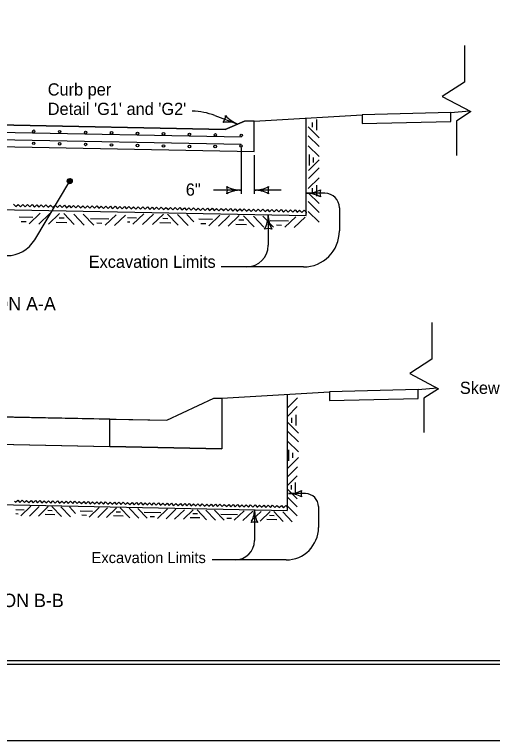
# Model space of a CAD drawing. Extents: x 10028 to 81668, y 6395 to 11634.
# Drawn here: x 14605 to 15231, y 7825 to 8776 of the extents above; entities that cross this region are included whole.
import ezdxf

# ---------------------------------------------------------------- set-up
doc = ezdxf.new("R2010")
doc.units = 0
for name, color, linetype in [('Default', 7, 'Continuous'), ('dsnCellElements', 7, 'Continuous'), ('dsnstdblockInterim', 7, 'Continuous'), ('dsnStdDimension', 7, 'Continuous'), ('ShtPlotIdentification', 7, 'Continuous')]:
    doc.layers.add(name, color=color, linetype=linetype)

msp = doc.modelspace()

# ---------------------------------------------------------------- linework, layer by layer
at = {"layer": 'Default'}
msp.add_lwpolyline([(13732.53, 9944.02), (16867.53, 9944.02), (16867.53, 7924.02), (13732.53, 7924.02)], close=True, dxfattribs=at)
at = {"layer": 'dsnCellElements'}
msp.add_line((14901.95, 8605.39), (14170.4, 8618.94), dxfattribs=at)
at = {"layer": 'dsnstdblockInterim'}
msp.add_lwpolyline([(13732.53, 9939.02), (16867.53, 9939.02), (16867.53, 7929.02), (13732.53, 7929.02)], close=True, dxfattribs=at)
at = {"layer": 'dsnStdDimension'}
msp.add_lwpolyline([(13628.03, 7824.52), (16972.03, 7824.52), (16972.03, 10408.52), (13628.03, 10408.52)], close=True, dxfattribs=at)
at = {"layer": 'ShtPlotIdentification'}
for p, q in [((15194.49, 8734.93), (15194.49, 8687.1)), ((15194.49, 8687.1), (15165.49, 8668.29)), ((15165.49, 8668.29), (15203.08, 8648.41)), ((15176.62, 8647.27), (15201.26, 8649.37)), ((15203.08, 8648.41), (15184.06, 8635.97)), ((14880.69, 8625.23), (14170.44, 8639.49)), ((14170.44, 8639.49), (14880.69, 8625.23)), ((14867.19, 8643.4), (14897.51, 8632.2)), ((14987.03, 8512.31), (14987.03, 8639.89)), ((14170.4, 8630), (14902.07, 8615.32)), ((14906.21, 8635.81), (14880.69, 8625.23)), ((14880.69, 8625.23), (14906.21, 8635.81)), ((14918.97, 8635.81), (14906.21, 8635.81)), ((14918.97, 8635.81), (14906.21, 8635.81)), ((14918.97, 8596.1), (14918.97, 8635.81)), ((14918.97, 8596.1), (14918.97, 8635.81)), ((14989.84, 8628.45), (15003.98, 8614.31)), ((15184.06, 8635.97), (15184.06, 8591.14)), ((14169.87, 8611.13), (14918.97, 8596.1)), ((14171.01, 8611.11), (14918.97, 8596.1)), ((14989.84, 8616.87), (15003.98, 8602.73)), ((14901.96, 8601.62), (14901.96, 8540.88)), ((14989.84, 8603.81), (15003.98, 8589.67)), ((14918.97, 8591.37), (14918.97, 8540.88)), ((14990.06, 8571.37), (15004.21, 8585.51)), ((14990.06, 8560.63), (15004.21, 8574.77)), ((14989.84, 8547.62), (15003.98, 8561.76)), ((14631.09, 8480.48), (14677.11, 8557.45)), ((14901.96, 8545.6), (14865.42, 8545.6)), ((14954.19, 8545.6), (14918.97, 8545.6)), ((14989.84, 8542.21), (15003.98, 8528.07)), ((15011.75, 8541.48), (14987.03, 8541.48)), ((14170.44, 8528.7), (14987.03, 8512.31)), ((14989.84, 8530.63), (15003.98, 8516.49)), ((15030.66, 8522.57), (15030.66, 8492.21)), ((14638.36, 8515.4), (14623.94, 8501.55)), ((14650.8, 8514.93), (14636.38, 8501.07)), ((14663.81, 8514.89), (14649.39, 8501.03)), ((14669.22, 8514.78), (14683.08, 8500.36)), ((14682.23, 8514.29), (14696.08, 8499.87)), ((14694.68, 8514.27), (14708.53, 8499.85)), ((14737.89, 8513.4), (14723.47, 8499.55)), ((14774.43, 8514.76), (14760.01, 8500.91)), ((14786.87, 8514.29), (14772.45, 8500.43)), ((14799.88, 8514.25), (14785.46, 8500.4)), ((14805.29, 8514.14), (14819.15, 8499.72)), ((14818.3, 8513.66), (14832.15, 8499.23)), ((14830.75, 8513.63), (14839.85, 8504.16)), ((14937.35, 8513.31), (14937.35, 8473.3)), ((14989.84, 8517.57), (15003.98, 8503.43)), ((14750.34, 8512.93), (14735.91, 8499.07)), ((14873.96, 8512.76), (14859.54, 8498.91)), ((14886.41, 8512.29), (14871.98, 8498.43)), ((14899.42, 8512.25), (14884.99, 8498.4)), ((14904.83, 8512.14), (14918.68, 8497.72)), ((14917.83, 8511.66), (14931.68, 8497.23)), ((14930.28, 8511.63), (14944.14, 8497.21)), ((14973.5, 8510.77), (14959.07, 8496.91)), ((14985.94, 8510.29), (14971.52, 8496.44)), ((14983.39, 8444.95), (14875.63, 8444.95)), ((15151.88, 8371.97), (15151.88, 8324.14)), ((15151.88, 8324.14), (15122.88, 8305.33)), ((15122.88, 8305.33), (15160.47, 8285.45)), ((15134.01, 8284.31), (15158.65, 8286.41)), ((15160.47, 8285.45), (15141.45, 8273.01)), ((14962.76, 8126.08), (14962.76, 8278.03)), ((14962.97, 8260.91), (14975.69, 8273.64)), ((15141.45, 8273.01), (15141.45, 8228.18)), ((14962.76, 8249.21), (14975.49, 8261.93)), ((14729.51, 8245.72), (14393.87, 8252.46)), ((14393.87, 8252.46), (14804.18, 8244.22)), ((14729.51, 8209.71), (14729.51, 8245.72)), ((14962.77, 8241.43), (14976.91, 8227.29)), ((14962.77, 8229.86), (14976.91, 8215.72)), ((14393.87, 8216.45), (14729.51, 8209.71)), ((14393.87, 8216.45), (14876.36, 8206.77)), ((14962.77, 8216.8), (14976.91, 8202.66)), ((14962.75, 8180.96), (14976.9, 8195.1)), ((14962.97, 8170.26), (14975.69, 8182.99)), ((14962.76, 8158.55), (14975.49, 8171.28)), ((14962.76, 8153.68), (14975.49, 8140.96)), ((14962.76, 8143.27), (14975.49, 8130.54)), ((14986.28, 8147.92), (14964.03, 8147.92)), ((14393.87, 8137.48), (14962.76, 8126.06)), ((14625.96, 8131.49), (14612.98, 8119.02)), ((14637.15, 8131.07), (14624.17, 8118.6)), ((14648.86, 8131.03), (14635.88, 8118.56)), ((14653.73, 8130.94), (14666.2, 8117.96)), ((14665.43, 8130.5), (14677.9, 8117.52)), ((14676.64, 8130.48), (14684.83, 8121.95)), ((14715.53, 8129.7), (14702.55, 8117.23)), ((14726.73, 8129.27), (14713.75, 8116.8)), ((14738.44, 8129.24), (14725.46, 8116.77)), ((14743.31, 8129.14), (14755.78, 8116.16)), ((14755.01, 8128.7), (14767.48, 8115.72)), ((14766.22, 8128.68), (14778.69, 8115.7)), ((14805.11, 8127.9), (14792.13, 8115.43)), ((14816.31, 8127.47), (14803.33, 8115)), ((14827.39, 8126.91), (14814.41, 8114.44)), ((14839.1, 8126.88), (14826.12, 8114.41)), ((14843.97, 8126.78), (14856.44, 8113.8)), ((14855.67, 8126.34), (14868.14, 8113.36)), ((14866.88, 8126.32), (14879.35, 8113.34)), ((14905.77, 8125.54), (14892.79, 8113.07)), ((14916.97, 8125.11), (14903.99, 8112.64)), ((14928.08, 8124.56), (14915.1, 8112.09)), ((14919.31, 8126.94), (14919.31, 8086.57)), ((14939.79, 8124.53), (14926.81, 8112.06)), ((14944.66, 8124.43), (14957.13, 8111.45)), ((14956.36, 8123.99), (14968.83, 8111.01)), ((14962.76, 8131.51), (14975.49, 8118.78)), ((15003.29, 8130.9), (15003.29, 8103.58)), ((14960.75, 8061.04), (14863.76, 8061.04))]:
    msp.add_line(p, q, dxfattribs=at)
for points in [[(14918.97, 8635.81), (15060.41, 8644.3), (15060.41, 8633.08), (15176.62, 8635.6), (15176.62, 8647.27), (15060.41, 8644.3)], [(15001.19, 8624.06), (15001.19, 8638.25)], [(14995.34, 8627.89), (14995.34, 8634.42)], [(14991.64, 8578.06), (14991.64, 8592.25)], [(14996.73, 8581.89), (14996.73, 8588.42)], [(14676.85, 8554.41), (14677.97, 8554.91), (14679.7, 8555.45), (14680.04, 8557.21), (14679.8, 8558.76), (14678.69, 8560.19), (14677.04, 8560.05), (14675.29, 8559.8), (14674.46, 8558.41), (14674.31, 8556.95), (14675.33, 8555.03), (14676.61, 8554.87), (14678.34, 8555.31), (14679.77, 8556.43), (14679.72, 8558.08), (14678.61, 8559.41), (14677.05, 8559.56), (14675.31, 8559.22), (14675.05, 8558.23), (14674.7, 8557.06), (14675.51, 8555.62), (14676.78, 8555.66), (14678.23, 8555.9), (14679.27, 8556.7), (14678.75, 8558.15), (14677.65, 8558.99), (14676.19, 8559.05), (14675.82, 8558.26), (14675.36, 8557.37), (14676.08, 8556.22), (14677.16, 8555.96), (14678.12, 8556.47), (14678.18, 8557.55), (14677.67, 8558.31), (14676.69, 8558.58), (14676.22, 8558.17), (14675.94, 8557.58), (14676.45, 8556.72), (14677.14, 8556.54), (14677.81, 8556.95), (14677.7, 8557.53), (14677.2, 8557.91), (14676.52, 8557.89), (14676.53, 8557.4), (14677.12, 8557.13)], [(15001.19, 8537.82), (15001.19, 8552.01)], [(14995.34, 8541.65), (14995.34, 8548.18)], [(14603.52, 8527.05), (14606.49, 8523.96), (14609.57, 8526.93), (14612.53, 8523.84), (14615.62, 8526.8), (14618.58, 8523.72), (14621.67, 8526.68), (14624.63, 8523.6), (14627.72, 8526.56), (14630.68, 8523.48), (14633.77, 8526.44), (14636.73, 8523.36), (14639.81, 8526.32), (14642.78, 8523.23), (14645.86, 8526.2), (14648.83, 8523.11), (14651.91, 8526.08), (14654.88, 8522.99), (14657.96, 8525.96), (14659.44, 8524.41)], [(14659.44, 8524.41), (14660.92, 8522.87), (14664.01, 8525.83), (14666.98, 8522.75), (14670.06, 8525.71), (14673.02, 8522.62), (14676.11, 8525.59), (14679.07, 8522.51), (14682.16, 8525.47), (14685.12, 8522.39), (14688.2, 8525.35), (14691.17, 8522.26), (14694.25, 8525.22), (14697.22, 8522.14), (14700.3, 8525.1), (14703.27, 8522.02), (14706.35, 8524.99), (14709.32, 8521.9), (14712.4, 8524.86), (14715.36, 8521.78), (14718.45, 8524.74), (14721.41, 8521.65), (14724.5, 8524.62), (14727.46, 8521.53), (14730.55, 8524.5), (14732.03, 8522.95)], [(14732.03, 8522.95), (14733.51, 8521.41), (14736.6, 8524.38), (14739.56, 8521.29), (14742.64, 8524.25), (14745.61, 8521.17), (14748.69, 8524.13), (14751.66, 8521.05), (14754.74, 8524.01), (14757.71, 8520.93), (14760.79, 8523.89), (14763.75, 8520.81), (14766.84, 8523.77), (14769.8, 8520.68), (14772.89, 8523.65), (14775.85, 8520.56), (14778.94, 8523.53), (14781.9, 8520.44), (14784.99, 8523.41), (14787.95, 8520.32), (14791.03, 8523.28), (14793.99, 8520.2), (14797.08, 8523.16), (14800.05, 8520.08), (14803.13, 8523.04), (14804.61, 8521.5)], [(14804.61, 8521.5), (14806.1, 8519.96), (14809.18, 8522.92), (14812.14, 8519.84), (14815.23, 8522.8), (14818.19, 8519.71), (14821.28, 8522.68), (14824.24, 8519.59), (14827.33, 8522.56), (14830.29, 8519.47), (14833.38, 8522.43), (14836.34, 8519.35), (14839.42, 8522.31), (14842.38, 8519.23), (14845.47, 8522.19), (14848.44, 8519.11), (14851.52, 8522.07), (14854.49, 8518.99), (14857.57, 8521.95), (14860.53, 8518.86), (14863.62, 8521.83), (14866.58, 8518.74), (14869.66, 8521.71), (14872.63, 8518.62), (14875.71, 8521.59), (14877.2, 8520.04)], [(14877.2, 8520.04), (14878.68, 8518.5), (14881.77, 8521.46), (14884.73, 8518.38), (14887.81, 8521.34), (14890.77, 8518.25), (14893.86, 8521.22), (14896.82, 8518.13), (14899.91, 8521.1), (14902.87, 8518.02), (14905.96, 8520.98), (14908.92, 8517.89), (14912.01, 8520.85), (14914.97, 8517.77), (14918.05, 8520.73), (14921.02, 8517.65), (14924.1, 8520.62), (14927.07, 8517.53), (14930.16, 8520.49), (14933.12, 8517.41), (14936.2, 8520.37), (14939.17, 8517.28), (14942.25, 8520.25), (14945.21, 8517.16), (14948.3, 8520.13), (14949.78, 8518.58)], [(14949.78, 8518.58), (14951.26, 8517.05), (14954.35, 8520.01), (14957.32, 8516.92), (14960.4, 8519.88), (14963.36, 8516.8), (14966.45, 8519.76), (14969.41, 8516.68), (14972.49, 8519.64), (14975.46, 8516.56), (14978.54, 8519.52), (14981.51, 8516.44), (14984.6, 8519.4), (14987.56, 8516.31), (14987.78, 8516.5)], [(14610.61, 8510.48), (14628.67, 8510.12)], [(14613.26, 8504.63), (14619.79, 8504.5)], [(14659.2, 8503.63), (14673.39, 8503.34)], [(14663.14, 8509.4), (14669.68, 8509.27)], [(14704.15, 8508.6), (14728.2, 8508.12)], [(14752.6, 8503.92), (14755.86, 8503.86)], [(14752.71, 8509.72), (14764.74, 8509.48)], [(14799.21, 8508.77), (14805.75, 8508.63)], [(14846.21, 8507.85), (14864.27, 8507.48)], [(14898.75, 8506.77), (14905.28, 8506.64)], [(14939.75, 8505.97), (14963.81, 8505.48)], [(14712.79, 8502.63), (14719.32, 8502.5)], [(14795.27, 8502.99), (14809.46, 8502.7)], [(14848.86, 8501.99), (14855.39, 8501.86)], [(14894.8, 8500.99), (14908.99, 8500.7)], [(14948.4, 8499.99), (14954.93, 8499.86)], [(14876.36, 8272.85), (15017.8, 8281.34), (15017.8, 8270.12), (15134.01, 8272.64), (15134.01, 8284.31), (15017.8, 8281.34)], [(14804.18, 8244.22), (14865.86, 8272.85), (14876.36, 8272.85), (14876.36, 8206.77)], [(14968.27, 8240.87), (14968.27, 8247.41)], [(14974.12, 8237.04), (14974.12, 8251.24)], [(14964.57, 8191.04), (14964.57, 8205.24)], [(14969.66, 8194.88), (14969.66, 8201.41)], [(14972.98, 8149.73), (14972.98, 8162.5)], [(14967.71, 8153.18), (14967.71, 8159.06)], [(14604.65, 8138.03), (14606.06, 8136.56), (14609, 8139.38), (14611.82, 8136.44), (14614.76, 8139.26), (14617.58, 8136.33), (14620.52, 8139.15), (14623.34, 8136.21), (14626.27, 8139.03), (14629.1, 8136.09), (14632.03, 8138.92), (14634.86, 8135.98), (14637.79, 8138.8), (14640.61, 8135.86), (14643.55, 8138.69), (14646.37, 8135.75), (14649.31, 8138.57), (14652.13, 8135.63), (14655.07, 8138.45), (14657.89, 8135.52), (14660.83, 8138.34), (14663.65, 8135.4), (14666.59, 8138.22), (14669.41, 8135.29), (14672.35, 8138.11), (14673.76, 8136.64)], [(14673.76, 8136.64), (14675.17, 8135.17), (14678.1, 8137.99), (14680.93, 8135.05), (14683.86, 8137.88), (14686.69, 8134.94), (14689.62, 8137.76), (14692.44, 8134.82), (14695.38, 8137.65), (14698.2, 8134.71), (14701.14, 8137.53), (14703.96, 8134.59), (14706.9, 8137.41), (14709.72, 8134.48), (14712.66, 8137.3), (14715.48, 8134.36), (14718.42, 8137.18), (14721.24, 8134.24), (14724.17, 8137.07), (14727, 8134.13), (14729.93, 8136.95), (14732.76, 8134.01), (14735.69, 8136.84), (14738.51, 8133.9), (14741.45, 8136.72), (14742.86, 8135.25)], [(14742.86, 8135.25), (14744.27, 8133.78), (14747.21, 8136.6), (14750.03, 8133.67), (14752.97, 8136.49), (14755.79, 8133.55), (14758.73, 8136.37), (14761.55, 8133.44), (14764.49, 8136.26), (14767.31, 8133.32), (14770.25, 8136.14), (14773.07, 8133.2), (14776, 8136.03), (14778.83, 8133.09), (14781.76, 8135.91), (14784.59, 8132.97), (14787.52, 8135.8), (14790.34, 8132.86), (14793.28, 8135.68), (14796.1, 8132.74), (14799.04, 8135.56), (14801.86, 8132.63), (14804.8, 8135.45), (14807.62, 8132.51), (14810.56, 8135.33), (14811.97, 8133.86)], [(14812.01, 8133.81), (14813.42, 8132.34), (14816.36, 8135.16), (14819.18, 8132.23), (14822.12, 8135.05), (14824.94, 8132.11), (14827.88, 8134.93), (14830.7, 8132), (14833.63, 8134.82), (14836.46, 8131.88), (14839.39, 8134.7), (14842.22, 8131.76), (14845.15, 8134.59), (14847.97, 8131.65), (14850.91, 8134.47), (14853.73, 8131.53), (14856.67, 8134.35), (14859.49, 8131.42), (14862.43, 8134.24), (14865.25, 8131.3), (14868.19, 8134.12), (14871.01, 8131.19), (14873.95, 8134.01), (14876.77, 8131.07), (14879.71, 8133.89), (14881.12, 8132.42)], [(14881.12, 8132.42), (14882.53, 8130.96), (14885.47, 8133.78), (14888.29, 8130.84), (14891.22, 8133.66), (14894.05, 8130.72), (14896.98, 8133.55), (14899.8, 8130.61), (14902.74, 8133.43), (14905.56, 8130.49), (14908.5, 8133.31), (14911.32, 8130.38), (14914.26, 8133.2), (14917.08, 8130.26), (14920.02, 8133.08), (14922.84, 8130.15), (14925.78, 8132.97), (14928.6, 8130.03), (14931.54, 8132.85), (14934.36, 8129.92), (14937.29, 8132.74), (14940.12, 8129.8), (14943.05, 8132.62), (14945.87, 8129.68), (14948.81, 8132.51), (14950.22, 8131.04)], [(14606.41, 8126.96), (14617.23, 8126.74)], [(14648.26, 8126.1), (14654.14, 8125.98)], [(14690.56, 8125.27), (14706.81, 8124.94)], [(14737.84, 8124.3), (14743.72, 8124.18)], [(14774.74, 8123.58), (14796.39, 8123.14)], [(14950.22, 8131.04), (14951.63, 8129.57), (14954.57, 8132.39), (14957.39, 8129.45), (14960.33, 8132.27), (14962.69, 8129.82)], [(14606.3, 8121.74), (14609.24, 8121.68)], [(14644.71, 8120.9), (14657.48, 8120.64)], [(14692.94, 8120), (14698.82, 8119.88)], [(14734.29, 8119.1), (14747.06, 8118.84)], [(14782.52, 8118.2), (14788.4, 8118.08)], [(14834.95, 8116.74), (14847.72, 8116.48)], [(14838.5, 8121.94), (14844.38, 8121.82)], [(14875.4, 8121.22), (14897.05, 8120.79)], [(14883.18, 8115.84), (14889.06, 8115.73)], [(14935.64, 8114.39), (14948.41, 8114.13)], [(14939.19, 8119.59), (14945.07, 8119.47)]]:
    msp.add_lwpolyline(points, dxfattribs=at)
msp.add_lwpolyline([(14876.36, 8206.77), (14729.51, 8209.71), (14729.51, 8245.72), (14804.18, 8244.22), (14865.86, 8272.85), (14876.36, 8272.85)], close=True, dxfattribs=at)
for centre, radius in [((14629.8, 8622.76), 1.65), ((14663.83, 8622.08), 1.65), ((14697.86, 8621.4), 1.65), ((14731.9, 8620.71), 1.65), ((14765.93, 8620.03), 1.65), ((14799.96, 8619.34), 1.65), ((14833.99, 8618.66), 1.65), ((14868.03, 8617.98), 1.65), ((14902.06, 8617.3), 1.65), ((14629.79, 8606.88), 1.65), ((14663.83, 8606.2), 1.65), ((14697.86, 8605.51), 1.65), ((14731.89, 8604.83), 1.65), ((14765.93, 8604.14), 1.65), ((14799.96, 8603.46), 1.65), ((14833.99, 8602.78), 1.65), ((14867.7, 8602.78), 1.65), ((14901.73, 8603.46), 1.65), ((14677.11, 8557.45), 3.31)]:
    msp.add_circle(centre, radius, dxfattribs=at)
for centre, radius, start, end in [((14834.42, 8554.74), 94.53, 69.71228, 87.98563), ((14865.91, 8643.88), 15.52, 321.9793, 357.446), ((14911.44, 8669.88), 40.18, 221.64016, 249.71265), ((14883.58, 8594.52), 40.18, 69.71265, 97.78514), ((14868.27, 8545.6), 15.52, 342.26665, 17.73335), ((14901.96, 8585.78), 40.18, 241.92751, 270), ((14901.96, 8505.43), 40.18, 90, 118.07249), ((14918.97, 8585.78), 40.18, 270, 298.07249), ((14918.97, 8505.43), 40.18, 61.92751, 90), ((14952.66, 8545.6), 15.52, 162.26665, 197.73335), ((14987.03, 8581.65), 40.18, 270, 298.07249), ((15020.72, 8541.48), 15.52, 162.26665, 197.73335), ((14987.03, 8501.3), 40.18, 61.92751, 90), ((15011.75, 8522.57), 18.91, 0, 90), ((14897.17, 8513.31), 40.18, 331.92751, 360), ((14977.52, 8513.31), 40.18, 180, 208.07249), ((14937.35, 8479.62), 15.52, 72.26665, 107.73335), ((14983.39, 8492.21), 47.27, 270, 360), ((14594.58, 8502.31), 42.54, 270, 329.12488), ((14908.99, 8473.3), 28.36, 270, 360), ((14964.03, 8184.08), 36.16, 270, 298.07249), ((14964.04, 8184.08), 36.16, 270, 298.07249), ((14994.35, 8147.92), 13.97, 162.26665, 197.73335), ((14994.36, 8147.92), 13.97, 162.26665, 197.73335), ((14964.03, 8111.76), 36.16, 61.92751, 90), ((14964.04, 8111.76), 36.16, 61.92751, 90), ((14986.28, 8130.9), 17.02, 0, 90), ((14883.15, 8126.94), 36.16, 331.92751, 360), ((14955.47, 8126.94), 36.16, 180, 208.07249), ((14919.31, 8096.62), 13.97, 72.26665, 107.73335), ((14960.75, 8103.58), 42.54, 270, 360), ((14893.79, 8086.56), 25.52, 270, 360)]:
    msp.add_arc(centre, radius, start, end, dxfattribs=at)

# ---------------------------------------------------------------- texts
at = {"layer": 'dsnCellElements'}
for s, height, p in [('Curb per ', 16, (14648.24, 8669.55)), ("Detail 'G1' and 'G2'", 16, (14648.24, 8644.09)), ('6"', 16, (14829.23, 8538.35)), ('Excavation Limits', 16, (14701.92, 8443.78)), ('Skew Angle', 16, (15188.61, 8278.56)), ('Excavation Limits', 14.4, (14705.68, 8056.94))]:
    msp.add_text(s, height=height, dxfattribs=at).set_placement(p)
at = {"layer": 'ShtPlotIdentification'}
for s, p in [('SECTION A-A', (14509.31, 8387.94)), ('SECTION B-B', (14519.72, 7999.36))]:
    msp.add_text(s, height=17.5, dxfattribs=at).set_placement(p)

doc.saveas('drawing.dxf')
